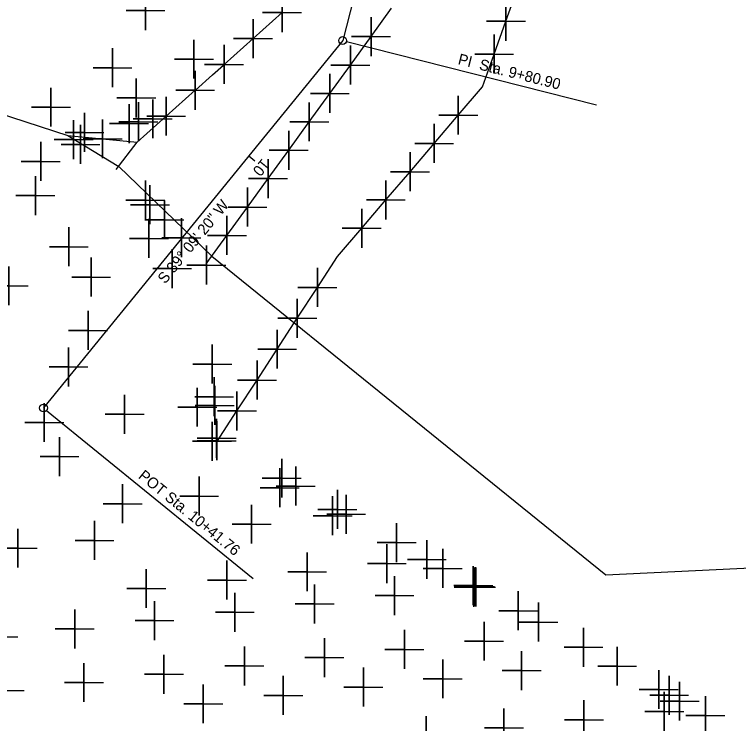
# Model space of a CAD drawing. Extents: x 2260968 to 2264340, y 653057 to 655850.
# Drawn here: x 2261691.8 to 2261784.8, y 654726.1 to 654817.2 of the extents above; entities that cross this region are included whole.
import ezdxf

# ---------------------------------------------------------------- set-up
doc = ezdxf.new("R2010")
doc.units = 0
for name, color, linetype in [('CL_X_Construction', 7, 'Continuous'), ('Default', 7, 'Continuous'), ('GE_X_CL_10', 7, 'Continuous')]:
    doc.layers.add(name, color=color, linetype=linetype)

msp = doc.modelspace()

# ---------------------------------------------------------------- linework, layer by layer
at = {"layer": 'CL_X_Construction'}
for p, q in [((2261743.195, 654850.138), (2261734.002, 654813.881)), ((2261743.195, 654850.138), (2261734.002, 654813.881)), ((2261734.002, 654813.881), (2261695.569, 654766.683)), ((2261734.002, 654813.881), (2261695.569, 654766.683))]:
    msp.add_line(p, q, dxfattribs=at)
at = {"layer": 'Default'}
for points in [[(2261618.54, 654827.787), (2261698.704, 654801.666), (2261705.249, 654797.682), (2261717.185, 654786.2), (2261767.784, 654745.234), (2261993.705, 654756.177)], [(2261708.67, 654817.73), (2261708.67, 654820.23), (2261708.67, 654817.73), (2261706.17, 654817.73), (2261708.67, 654817.73), (2261708.67, 654815.23), (2261708.67, 654817.73), (2261711.17, 654817.73)], [(2261717.829, 654762.332), (2261720.413, 654766.3), (2261722.996, 654770.267), (2261725.58, 654774.235), (2261728.164, 654778.203), (2261730.748, 654782.171), (2261733.331, 654786.138), (2261736.435, 654789.769), (2261739.539, 654793.4), (2261742.642, 654797.031), (2261745.746, 654800.661), (2261748.85, 654804.292), (2261751.953, 654807.923), (2261753.456, 654812.144), (2261754.959, 654816.366), (2261756.461, 654820.587)], [(2261726.2, 654817.465), (2261726.2, 654819.965), (2261726.2, 654817.465), (2261723.7, 654817.465), (2261726.2, 654817.465), (2261726.2, 654814.965), (2261726.2, 654817.465), (2261728.7, 654817.465)], [(2261754.959, 654816.366), (2261754.959, 654818.866), (2261754.959, 654816.366), (2261752.459, 654816.366), (2261754.959, 654816.366), (2261754.959, 654813.866), (2261754.959, 654816.366), (2261757.459, 654816.366)], [(2261704.9, 654797.337), (2261707.603, 654800.837), (2261711.322, 654804.163), (2261715.042, 654807.488), (2261715.067, 654807.511), (2261717.287, 654809.496), (2261718.67, 654810.732), (2261718.761, 654810.814), (2261722.48, 654814.139), (2261726.2, 654817.465)], [(2261716.479, 654785.196), (2261719.123, 654788.845), (2261721.768, 654792.493), (2261724.413, 654796.142), (2261727.057, 654799.79), (2261729.702, 654803.439), (2261732.346, 654807.088), (2261734.991, 654810.736), (2261737.636, 654814.385), (2261740.28, 654818.033)], [(2261722.48, 654814.139), (2261722.48, 654816.639), (2261722.48, 654814.139), (2261719.98, 654814.139), (2261722.48, 654814.139), (2261722.48, 654811.639), (2261722.48, 654814.139), (2261724.98, 654814.139)], [(2261737.636, 654814.385), (2261737.636, 654816.885), (2261737.636, 654814.385), (2261735.136, 654814.385), (2261737.636, 654814.385), (2261737.636, 654811.885), (2261737.636, 654814.385), (2261740.136, 654814.385)], [(2261753.456, 654812.144), (2261753.456, 654814.644), (2261753.456, 654812.144), (2261750.956, 654812.144), (2261753.456, 654812.144), (2261753.456, 654809.644), (2261753.456, 654812.144), (2261755.956, 654812.144)], [(2261714.89, 654811.49), (2261714.89, 654813.99), (2261714.89, 654811.49), (2261712.39, 654811.49), (2261714.89, 654811.49), (2261714.89, 654808.99), (2261714.89, 654811.49), (2261717.39, 654811.49)], [(2261704.43, 654810.39), (2261704.43, 654812.89), (2261704.43, 654810.39), (2261701.93, 654810.39), (2261704.43, 654810.39), (2261704.43, 654807.89), (2261704.43, 654810.39), (2261706.93, 654810.39)], [(2261718.761, 654810.814), (2261718.761, 654813.314), (2261718.761, 654810.814), (2261716.261, 654810.814), (2261718.761, 654810.814), (2261718.761, 654808.314), (2261718.761, 654810.814), (2261721.261, 654810.814)], [(2261734.991, 654810.736), (2261734.991, 654813.236), (2261734.991, 654810.736), (2261732.491, 654810.736), (2261734.991, 654810.736), (2261734.991, 654808.236), (2261734.991, 654810.736), (2261737.491, 654810.736)], [(2261715.042, 654807.488), (2261715.042, 654809.988), (2261715.042, 654807.488), (2261712.542, 654807.488), (2261715.042, 654807.488), (2261715.042, 654804.988), (2261715.042, 654807.488), (2261717.542, 654807.488)], [(2261732.346, 654807.088), (2261732.346, 654809.588), (2261732.346, 654807.088), (2261729.846, 654807.088), (2261732.346, 654807.088), (2261732.346, 654804.588), (2261732.346, 654807.088), (2261734.846, 654807.088)], [(2261707.48, 654806.51), (2261707.48, 654809.01), (2261707.48, 654806.51), (2261704.98, 654806.51), (2261707.48, 654806.51), (2261707.48, 654804.01), (2261707.48, 654806.51), (2261709.98, 654806.51)], [(2261696.52, 654805.32), (2261696.52, 654807.82), (2261696.52, 654805.32), (2261694.02, 654805.32), (2261696.52, 654805.32), (2261696.52, 654802.82), (2261696.52, 654805.32), (2261699.02, 654805.32)], [(2261709.589, 654803.82), (2261709.589, 654806.32), (2261709.589, 654803.82), (2261707.089, 654803.82), (2261709.589, 654803.82), (2261709.589, 654801.32), (2261709.589, 654803.82), (2261712.089, 654803.82)], [(2261711.322, 654804.163), (2261711.322, 654806.663), (2261711.322, 654804.163), (2261708.822, 654804.163), (2261711.322, 654804.163), (2261711.322, 654801.663), (2261711.322, 654804.163), (2261713.822, 654804.163)], [(2261748.85, 654804.292), (2261748.85, 654806.792), (2261748.85, 654804.292), (2261746.35, 654804.292), (2261748.85, 654804.292), (2261748.85, 654801.792), (2261748.85, 654804.292), (2261751.35, 654804.292)], [(2261706.554, 654803.219), (2261706.554, 654805.719), (2261706.554, 654803.219), (2261704.054, 654803.219), (2261706.554, 654803.219), (2261706.554, 654800.719), (2261706.554, 654803.219), (2261709.054, 654803.219)], [(2261707.754, 654803.457), (2261707.754, 654805.957), (2261707.754, 654803.457), (2261705.254, 654803.457), (2261707.754, 654803.457), (2261707.754, 654800.957), (2261707.754, 654803.457), (2261710.254, 654803.457)], [(2261729.702, 654803.439), (2261729.702, 654805.939), (2261729.702, 654803.439), (2261727.202, 654803.439), (2261729.702, 654803.439), (2261729.702, 654800.939), (2261729.702, 654803.439), (2261732.202, 654803.439)], [(2261700.827, 654802.086), (2261700.827, 654804.586), (2261700.827, 654802.086), (2261698.327, 654802.086), (2261700.827, 654802.086), (2261700.827, 654799.586), (2261700.827, 654802.086), (2261703.327, 654802.086)], [(2261699.431, 654801.157), (2261699.431, 654803.657), (2261699.431, 654801.157), (2261696.931, 654801.157), (2261699.431, 654801.157), (2261699.431, 654798.657), (2261699.431, 654801.157), (2261701.931, 654801.157)], [(2261703.154, 654801.251), (2261703.154, 654803.751), (2261703.154, 654801.251), (2261700.654, 654801.251), (2261703.154, 654801.251), (2261703.154, 654798.751), (2261703.154, 654801.251), (2261705.654, 654801.251)], [(2261700.314, 654800.541), (2261700.314, 654803.041), (2261700.314, 654800.541), (2261697.814, 654800.541), (2261700.314, 654800.541), (2261700.314, 654798.041), (2261700.314, 654800.541), (2261702.814, 654800.541)], [(2261745.746, 654800.661), (2261745.746, 654803.161), (2261745.746, 654800.661), (2261743.246, 654800.661), (2261745.746, 654800.661), (2261745.746, 654798.161), (2261745.746, 654800.661), (2261748.246, 654800.661)], [(2261698.704, 654801.666), (2261703.154, 654801.251), (2261707.603, 654800.837)], [(2261727.057, 654799.79), (2261727.057, 654802.29), (2261727.057, 654799.79), (2261724.557, 654799.79), (2261727.057, 654799.79), (2261727.057, 654797.29), (2261727.057, 654799.79), (2261729.557, 654799.79)], [(2261695.21, 654798.35), (2261695.21, 654800.85), (2261695.21, 654798.35), (2261692.71, 654798.35), (2261695.21, 654798.35), (2261695.21, 654795.85), (2261695.21, 654798.35), (2261697.71, 654798.35)], [(2261742.642, 654797.031), (2261742.642, 654799.531), (2261742.642, 654797.031), (2261740.142, 654797.031), (2261742.642, 654797.031), (2261742.642, 654794.531), (2261742.642, 654797.031), (2261745.142, 654797.031)], [(2261724.413, 654796.142), (2261724.413, 654798.642), (2261724.413, 654796.142), (2261721.913, 654796.142), (2261724.413, 654796.142), (2261724.413, 654793.642), (2261724.413, 654796.142), (2261726.913, 654796.142)], [(2261694.53, 654793.97), (2261694.53, 654796.47), (2261694.53, 654793.97), (2261692.03, 654793.97), (2261694.53, 654793.97), (2261694.53, 654791.47), (2261694.53, 654793.97), (2261697.03, 654793.97)], [(2261708.658, 654793.397), (2261708.658, 654795.897), (2261708.658, 654793.397), (2261706.158, 654793.397), (2261708.658, 654793.397), (2261708.658, 654790.897), (2261708.658, 654793.397), (2261711.158, 654793.397)], [(2261709.238, 654792.789), (2261709.238, 654795.289), (2261709.238, 654792.789), (2261706.738, 654792.789), (2261709.238, 654792.789), (2261709.238, 654790.289), (2261709.238, 654792.789), (2261711.738, 654792.789)], [(2261739.539, 654793.4), (2261739.539, 654795.9), (2261739.539, 654793.4), (2261737.039, 654793.4), (2261739.539, 654793.4), (2261739.539, 654790.9), (2261739.539, 654793.4), (2261742.039, 654793.4)], [(2261721.768, 654792.493), (2261721.768, 654794.993), (2261721.768, 654792.493), (2261719.268, 654792.493), (2261721.768, 654792.493), (2261721.768, 654789.993), (2261721.768, 654792.493), (2261724.268, 654792.493)], [(2261711.091, 654790.846), (2261711.091, 654793.346), (2261711.091, 654790.846), (2261708.591, 654790.846), (2261711.091, 654790.846), (2261711.091, 654788.346), (2261711.091, 654790.846), (2261713.591, 654790.846)], [(2261736.435, 654789.769), (2261736.435, 654792.269), (2261736.435, 654789.769), (2261733.935, 654789.769), (2261736.435, 654789.769), (2261736.435, 654787.269), (2261736.435, 654789.769), (2261738.935, 654789.769)], [(2261709.1, 654788.47), (2261709.1, 654790.97), (2261709.1, 654788.47), (2261706.6, 654788.47), (2261709.1, 654788.47), (2261709.1, 654785.97), (2261709.1, 654788.47), (2261711.6, 654788.47)], [(2261713.279, 654788.552), (2261713.279, 654791.052), (2261713.279, 654788.552), (2261710.779, 654788.552), (2261713.279, 654788.552), (2261713.279, 654786.052), (2261713.279, 654788.552), (2261715.779, 654788.552)], [(2261719.123, 654788.845), (2261719.123, 654791.345), (2261719.123, 654788.845), (2261716.623, 654788.845), (2261719.123, 654788.845), (2261719.123, 654786.345), (2261719.123, 654788.845), (2261721.623, 654788.845)], [(2261698.82, 654787.4), (2261698.82, 654789.9), (2261698.82, 654787.4), (2261696.32, 654787.4), (2261698.82, 654787.4), (2261698.82, 654784.9), (2261698.82, 654787.4), (2261701.32, 654787.4)], [(2261712.09, 654784.59), (2261712.09, 654787.09), (2261712.09, 654784.59), (2261709.59, 654784.59), (2261712.09, 654784.59), (2261712.09, 654782.09), (2261712.09, 654784.59), (2261714.59, 654784.59)], [(2261716.489, 654785.033), (2261716.489, 654787.533), (2261716.489, 654785.033), (2261713.989, 654785.033), (2261716.489, 654785.033), (2261716.489, 654782.533), (2261716.489, 654785.033), (2261718.989, 654785.033)], [(2261701.69, 654783.49), (2261701.69, 654785.99), (2261701.69, 654783.49), (2261699.19, 654783.49), (2261701.69, 654783.49), (2261701.69, 654780.99), (2261701.69, 654783.49), (2261704.19, 654783.49)], [(2261691.11, 654782.37), (2261691.11, 654784.87), (2261691.11, 654782.37), (2261688.61, 654782.37), (2261691.11, 654782.37), (2261691.11, 654779.87), (2261691.11, 654782.37), (2261693.61, 654782.37)], [(2261730.748, 654782.171), (2261730.748, 654784.671), (2261730.748, 654782.171), (2261728.248, 654782.171), (2261730.748, 654782.171), (2261730.748, 654779.671), (2261730.748, 654782.171), (2261733.248, 654782.171)], [(2261728.164, 654778.203), (2261728.164, 654780.703), (2261728.164, 654778.203), (2261725.664, 654778.203), (2261728.164, 654778.203), (2261728.164, 654775.703), (2261728.164, 654778.203), (2261730.664, 654778.203)], [(2261701.29, 654776.64), (2261701.29, 654779.14), (2261701.29, 654776.64), (2261698.79, 654776.64), (2261701.29, 654776.64), (2261701.29, 654774.14), (2261701.29, 654776.64), (2261703.79, 654776.64)], [(2261725.58, 654774.235), (2261725.58, 654776.735), (2261725.58, 654774.235), (2261723.08, 654774.235), (2261725.58, 654774.235), (2261725.58, 654771.735), (2261725.58, 654774.235), (2261728.08, 654774.235)], [(2261717.239, 654772.32), (2261717.239, 654774.82), (2261717.239, 654772.32), (2261714.739, 654772.32), (2261717.239, 654772.32), (2261717.239, 654769.82), (2261717.239, 654772.32), (2261719.739, 654772.32)], [(2261698.77, 654771.95), (2261698.77, 654774.45), (2261698.77, 654771.95), (2261696.27, 654771.95), (2261698.77, 654771.95), (2261698.77, 654769.45), (2261698.77, 654771.95), (2261701.27, 654771.95)], [(2261722.996, 654770.267), (2261722.996, 654772.767), (2261722.996, 654770.267), (2261720.496, 654770.267), (2261722.996, 654770.267), (2261722.996, 654767.767), (2261722.996, 654770.267), (2261725.496, 654770.267)], [(2261717.487, 654768.118), (2261717.487, 654770.618), (2261717.487, 654768.118), (2261714.987, 654768.118), (2261717.487, 654768.118), (2261717.487, 654765.618), (2261717.487, 654768.118), (2261719.987, 654768.118)], [(2261715.32, 654766.78), (2261715.32, 654769.28), (2261715.32, 654766.78), (2261712.82, 654766.78), (2261715.32, 654766.78), (2261715.32, 654764.28), (2261715.32, 654766.78), (2261717.82, 654766.78)], [(2261717.553, 654767.006), (2261717.553, 654769.506), (2261717.553, 654767.006), (2261715.053, 654767.006), (2261717.553, 654767.006), (2261717.553, 654764.506), (2261717.553, 654767.006), (2261720.053, 654767.006)], [(2261705.98, 654765.88), (2261705.98, 654768.38), (2261705.98, 654765.88), (2261703.48, 654765.88), (2261705.98, 654765.88), (2261705.98, 654763.38), (2261705.98, 654765.88), (2261708.48, 654765.88)], [(2261720.413, 654766.3), (2261720.413, 654768.8), (2261720.413, 654766.3), (2261717.913, 654766.3), (2261720.413, 654766.3), (2261720.413, 654763.8), (2261720.413, 654766.3), (2261722.913, 654766.3)], [(2261695.66, 654764.81), (2261695.66, 654767.31), (2261695.66, 654764.81), (2261693.16, 654764.81), (2261695.66, 654764.81), (2261695.66, 654762.31), (2261695.66, 654764.81), (2261698.16, 654764.81)], [(2261717.22, 654762.41), (2261717.22, 654764.91), (2261717.22, 654762.41), (2261714.72, 654762.41), (2261717.22, 654762.41), (2261717.22, 654759.91), (2261717.22, 654762.41), (2261719.72, 654762.41)], [(2261717.802, 654762.794), (2261717.802, 654765.294), (2261717.802, 654762.794), (2261715.302, 654762.794), (2261717.802, 654762.794), (2261717.802, 654760.294), (2261717.802, 654762.794), (2261720.302, 654762.794)], [(2261717.821, 654762.473), (2261717.821, 654764.973), (2261717.821, 654762.473), (2261715.321, 654762.473), (2261717.821, 654762.473), (2261717.821, 654759.973), (2261717.821, 654762.473), (2261720.321, 654762.473)], [(2261697.62, 654760.44), (2261697.62, 654762.94), (2261697.62, 654760.44), (2261695.12, 654760.44), (2261697.62, 654760.44), (2261697.62, 654757.94), (2261697.62, 654760.44), (2261700.12, 654760.44)], [(2261726.167, 654757.659), (2261726.167, 654760.159), (2261726.167, 654757.659), (2261723.667, 654757.659), (2261726.167, 654757.659), (2261726.167, 654755.159), (2261726.167, 654757.659), (2261728.667, 654757.659)], [(2261725.9, 654756.44), (2261725.9, 654758.94), (2261725.9, 654756.44), (2261723.4, 654756.44), (2261725.9, 654756.44), (2261725.9, 654753.94), (2261725.9, 654756.44), (2261728.4, 654756.44)], [(2261727.964, 654756.653), (2261727.964, 654759.153), (2261727.964, 654756.653), (2261725.464, 654756.653), (2261727.964, 654756.653), (2261727.964, 654754.153), (2261727.964, 654756.653), (2261730.464, 654756.653)], [(2261715.56, 654755.37), (2261715.56, 654757.87), (2261715.56, 654755.37), (2261713.06, 654755.37), (2261715.56, 654755.37), (2261715.56, 654752.87), (2261715.56, 654755.37), (2261718.06, 654755.37)], [(2261705.73, 654754.38), (2261705.73, 654756.88), (2261705.73, 654754.38), (2261703.23, 654754.38), (2261705.73, 654754.38), (2261705.73, 654751.88), (2261705.73, 654754.38), (2261708.23, 654754.38)], [(2261733.322, 654753.65), (2261733.322, 654756.15), (2261733.322, 654753.65), (2261730.822, 654753.65), (2261733.322, 654753.65), (2261733.322, 654751.15), (2261733.322, 654753.65), (2261735.822, 654753.65)], [(2261732.7, 654752.84), (2261732.7, 654755.34), (2261732.7, 654752.84), (2261730.2, 654752.84), (2261732.7, 654752.84), (2261732.7, 654750.34), (2261732.7, 654752.84), (2261735.2, 654752.84)], [(2261734.442, 654753.022), (2261734.442, 654755.522), (2261734.442, 654753.022), (2261731.942, 654753.022), (2261734.442, 654753.022), (2261734.442, 654750.522), (2261734.442, 654753.022), (2261736.942, 654753.022)], [(2261722.3, 654751.75), (2261722.3, 654754.25), (2261722.3, 654751.75), (2261719.8, 654751.75), (2261722.3, 654751.75), (2261722.3, 654749.25), (2261722.3, 654751.75), (2261724.8, 654751.75)], [(2261702.11, 654749.67), (2261702.11, 654752.17), (2261702.11, 654749.67), (2261699.61, 654749.67), (2261702.11, 654749.67), (2261702.11, 654747.17), (2261702.11, 654749.67), (2261704.61, 654749.67)], [(2261740.924, 654749.389), (2261740.924, 654751.889), (2261740.924, 654749.389), (2261738.424, 654749.389), (2261740.924, 654749.389), (2261740.924, 654746.889), (2261740.924, 654749.389), (2261743.424, 654749.389)], [(2261692.27, 654748.67), (2261692.27, 654751.17), (2261692.27, 654748.67), (2261689.77, 654748.67), (2261692.27, 654748.67), (2261692.27, 654746.17), (2261692.27, 654748.67), (2261694.77, 654748.67)], [(2261744.801, 654747.217), (2261744.801, 654749.717), (2261744.801, 654747.217), (2261742.301, 654747.217), (2261744.801, 654747.217), (2261744.801, 654744.717), (2261744.801, 654747.217), (2261747.301, 654747.217)], [(2261739.67, 654746.69), (2261739.67, 654749.19), (2261739.67, 654746.69), (2261737.17, 654746.69), (2261739.67, 654746.69), (2261739.67, 654744.19), (2261739.67, 654746.69), (2261742.17, 654746.69)], [(2261729.43, 654745.63), (2261729.43, 654748.13), (2261729.43, 654745.63), (2261726.93, 654745.63), (2261729.43, 654745.63), (2261729.43, 654743.13), (2261729.43, 654745.63), (2261731.93, 654745.63)], [(2261746.846, 654746.071), (2261746.846, 654748.571), (2261746.846, 654746.071), (2261744.346, 654746.071), (2261746.846, 654746.071), (2261746.846, 654743.571), (2261746.846, 654746.071), (2261749.346, 654746.071)], [(2261719.13, 654744.57), (2261719.13, 654747.07), (2261719.13, 654744.57), (2261716.63, 654744.57), (2261719.13, 654744.57), (2261719.13, 654742.07), (2261719.13, 654744.57), (2261721.63, 654744.57)], [(2261708.76, 654743.49), (2261708.76, 654745.99), (2261708.76, 654743.49), (2261706.26, 654743.49), (2261708.76, 654743.49), (2261708.76, 654740.99), (2261708.76, 654743.49), (2261711.26, 654743.49)], [(2261750.774, 654743.87), (2261750.774, 654746.37), (2261750.774, 654743.87), (2261748.274, 654743.87), (2261750.774, 654743.87), (2261750.774, 654741.37), (2261750.774, 654743.87), (2261753.274, 654743.87)], [(2261750.83, 654743.65), (2261750.83, 654746.15), (2261750.83, 654743.65), (2261748.33, 654743.65), (2261750.83, 654743.65), (2261750.83, 654741.15), (2261750.83, 654743.65), (2261753.33, 654743.65)], [(2261750.999, 654743.744), (2261750.999, 654746.244), (2261750.999, 654743.744), (2261748.499, 654743.744), (2261750.999, 654743.744), (2261750.999, 654741.244), (2261750.999, 654743.744), (2261753.499, 654743.744)], [(2261751.114, 654743.679), (2261751.114, 654746.179), (2261751.114, 654743.679), (2261748.614, 654743.679), (2261751.114, 654743.679), (2261751.114, 654741.179), (2261751.114, 654743.679), (2261753.614, 654743.679)], [(2261740.65, 654742.58), (2261740.65, 654745.08), (2261740.65, 654742.58), (2261738.15, 654742.58), (2261740.65, 654742.58), (2261740.65, 654740.08), (2261740.65, 654742.58), (2261743.15, 654742.58)], [(2261730.38, 654741.51), (2261730.38, 654744.01), (2261730.38, 654741.51), (2261727.88, 654741.51), (2261730.38, 654741.51), (2261730.38, 654739.01), (2261730.38, 654741.51), (2261732.88, 654741.51)], [(2261756.537, 654740.64), (2261756.537, 654743.14), (2261756.537, 654740.64), (2261754.037, 654740.64), (2261756.537, 654740.64), (2261756.537, 654738.14), (2261756.537, 654740.64), (2261759.037, 654740.64)], [(2261720.14, 654740.44), (2261720.14, 654742.94), (2261720.14, 654740.44), (2261717.64, 654740.44), (2261720.14, 654740.44), (2261720.14, 654737.94), (2261720.14, 654740.44), (2261722.64, 654740.44)], [(2261709.82, 654739.36), (2261709.82, 654741.86), (2261709.82, 654739.36), (2261707.32, 654739.36), (2261709.82, 654739.36), (2261709.82, 654736.86), (2261709.82, 654739.36), (2261712.32, 654739.36)], [(2261759.152, 654739.175), (2261759.152, 654741.675), (2261759.152, 654739.175), (2261756.652, 654739.175), (2261759.152, 654739.175), (2261759.152, 654736.675), (2261759.152, 654739.175), (2261761.652, 654739.175)], [(2261699.58, 654738.29), (2261699.58, 654740.79), (2261699.58, 654738.29), (2261697.08, 654738.29), (2261699.58, 654738.29), (2261699.58, 654735.79), (2261699.58, 654738.29), (2261702.08, 654738.29)], [(2261689.78, 654737.3), (2261689.78, 654739.8), (2261689.78, 654737.3), (2261687.28, 654737.3), (2261689.78, 654737.3), (2261689.78, 654734.8), (2261689.78, 654737.3), (2261692.28, 654737.3)], [(2261752.16, 654736.72), (2261752.16, 654739.22), (2261752.16, 654736.72), (2261749.66, 654736.72), (2261752.16, 654736.72), (2261752.16, 654734.22), (2261752.16, 654736.72), (2261754.66, 654736.72)], [(2261764.926, 654735.939), (2261764.926, 654738.439), (2261764.926, 654735.939), (2261762.426, 654735.939), (2261764.926, 654735.939), (2261764.926, 654733.439), (2261764.926, 654735.939), (2261767.426, 654735.939)], [(2261741.92, 654735.66), (2261741.92, 654738.16), (2261741.92, 654735.66), (2261739.42, 654735.66), (2261741.92, 654735.66), (2261741.92, 654733.16), (2261741.92, 654735.66), (2261744.42, 654735.66)], [(2261731.65, 654734.61), (2261731.65, 654737.11), (2261731.65, 654734.61), (2261729.15, 654734.61), (2261731.65, 654734.61), (2261731.65, 654732.11), (2261731.65, 654734.61), (2261734.15, 654734.61)], [(2261721.37, 654733.55), (2261721.37, 654736.05), (2261721.37, 654733.55), (2261718.87, 654733.55), (2261721.37, 654733.55), (2261721.37, 654731.05), (2261721.37, 654733.55), (2261723.87, 654733.55)], [(2261769.25, 654733.516), (2261769.25, 654736.016), (2261769.25, 654733.516), (2261766.75, 654733.516), (2261769.25, 654733.516), (2261769.25, 654731.016), (2261769.25, 654733.516), (2261771.75, 654733.516)], [(2261711.03, 654732.48), (2261711.03, 654734.98), (2261711.03, 654732.48), (2261708.53, 654732.48), (2261711.03, 654732.48), (2261711.03, 654729.98), (2261711.03, 654732.48), (2261713.53, 654732.48)], [(2261756.98, 654732.94), (2261756.98, 654735.44), (2261756.98, 654732.94), (2261754.48, 654732.94), (2261756.98, 654732.94), (2261756.98, 654730.44), (2261756.98, 654732.94), (2261759.48, 654732.94)], [(2261700.75, 654731.41), (2261700.75, 654733.91), (2261700.75, 654731.41), (2261698.25, 654731.41), (2261700.75, 654731.41), (2261700.75, 654728.91), (2261700.75, 654731.41), (2261703.25, 654731.41)], [(2261746.84, 654731.89), (2261746.84, 654734.39), (2261746.84, 654731.89), (2261744.34, 654731.89), (2261746.84, 654731.89), (2261746.84, 654729.39), (2261746.84, 654731.89), (2261749.34, 654731.89)], [(2261690.6, 654730.38), (2261690.6, 654732.88), (2261690.6, 654730.38), (2261688.1, 654730.38), (2261690.6, 654730.38), (2261690.6, 654727.88), (2261690.6, 654730.38), (2261693.1, 654730.38)], [(2261736.65, 654730.83), (2261736.65, 654733.33), (2261736.65, 654730.83), (2261734.15, 654730.83), (2261736.65, 654730.83), (2261736.65, 654728.33), (2261736.65, 654730.83), (2261739.15, 654730.83)], [(2261774.599, 654730.519), (2261774.599, 654733.019), (2261774.599, 654730.519), (2261772.099, 654730.519), (2261774.599, 654730.519), (2261774.599, 654728.019), (2261774.599, 654730.519), (2261777.099, 654730.519)], [(2261726.36, 654729.75), (2261726.36, 654732.25), (2261726.36, 654729.75), (2261723.86, 654729.75), (2261726.36, 654729.75), (2261726.36, 654727.25), (2261726.36, 654729.75), (2261728.86, 654729.75)], [(2261775.929, 654729.773), (2261775.929, 654732.273), (2261775.929, 654729.773), (2261773.429, 654729.773), (2261775.929, 654729.773), (2261775.929, 654727.273), (2261775.929, 654729.773), (2261778.429, 654729.773)], [(2261716.08, 654728.67), (2261716.08, 654731.17), (2261716.08, 654728.67), (2261713.58, 654728.67), (2261716.08, 654728.67), (2261716.08, 654726.17), (2261716.08, 654728.67), (2261718.58, 654728.67)], [(2261777.274, 654729.02), (2261777.274, 654731.52), (2261777.274, 654729.02), (2261774.774, 654729.02), (2261777.274, 654729.02), (2261777.274, 654726.52), (2261777.274, 654729.02), (2261779.774, 654729.02)], [(2261775.3, 654727.71), (2261775.3, 654730.21), (2261775.3, 654727.71), (2261772.8, 654727.71), (2261775.3, 654727.71), (2261775.3, 654725.21), (2261775.3, 654727.71), (2261777.8, 654727.71)], [(2261764.99, 654726.64), (2261764.99, 654729.14), (2261764.99, 654726.64), (2261762.49, 654726.64), (2261764.99, 654726.64), (2261764.99, 654724.14), (2261764.99, 654726.64), (2261767.49, 654726.64)], [(2261780.591, 654727.161), (2261780.591, 654729.661), (2261780.591, 654727.161), (2261778.091, 654727.161), (2261780.591, 654727.161), (2261780.591, 654724.661), (2261780.591, 654727.161), (2261783.091, 654727.161)], [(2261754.71, 654725.58), (2261754.71, 654728.08), (2261754.71, 654725.58), (2261752.21, 654725.58), (2261754.71, 654725.58), (2261754.71, 654723.08), (2261754.71, 654725.58), (2261757.21, 654725.58)], [(2261744.71, 654724.57), (2261744.71, 654727.07), (2261744.71, 654724.57), (2261742.21, 654724.57), (2261744.71, 654724.57), (2261744.71, 654722.07), (2261744.71, 654724.57), (2261747.21, 654724.57)]]:
    msp.add_lwpolyline(points, dxfattribs=at)
at = {"layer": 'GE_X_CL_10'}
for p, q in [((2261743.195, 654850.138), (2261734.002, 654813.881)), ((2261734.002, 654813.881), (2261695.569, 654766.683)), ((2261734.487, 654813.758), (2261766.614, 654805.613)), ((2261734.487, 654813.758), (2261766.614, 654805.613)), ((2261721.941, 654799.069), (2261722.716, 654798.437)), ((2261721.941, 654799.069), (2261722.716, 654798.437)), ((2261695.957, 654766.367), (2261722.486, 654744.765)), ((2261695.957, 654766.367), (2261722.486, 654744.765))]:
    msp.add_line(p, q, dxfattribs=at)
for centre in [(2261734.002, 654813.881), (2261734.002, 654813.881), (2261695.569, 654766.683), (2261695.569, 654766.683)]:
    msp.add_circle(centre, 0.5, dxfattribs=at)

# ---------------------------------------------------------------- texts
for s, rotation, p in [('PI  Sta. 9+80.90', 345.77269, (2261748.714, 654810.873)), ('PI  Sta. 9+80.90', 345.77269, (2261748.714, 654810.873)), ('10', 230.84442, (2261723.664, 654798.809)), ('10', 230.84442, (2261723.664, 654798.809)), ('S 39%%d 09\' 20" W', 50.84442, (2261711.184, 654782.533)), ('POT Sta. 10+41.76', 320.84442, (2261707.643, 654757.755)), ('POT Sta. 10+41.76', 320.84442, (2261707.643, 654757.755))]:
    msp.add_text(s, height=1.4, rotation=rotation, dxfattribs=at).set_placement(p)

doc.saveas('drawing.dxf')
